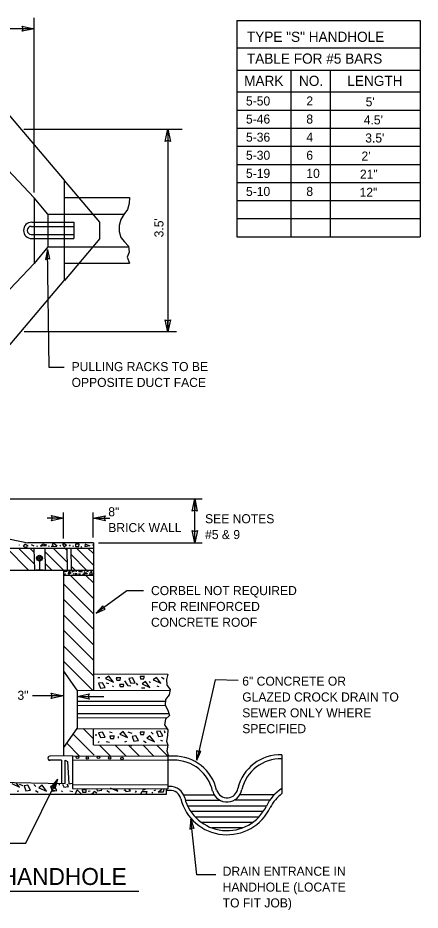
# Model space of a CAD drawing. Extents: x 19188 to 19495, y 20866 to 21061.
# Drawn here: x 19235.6 to 19272.9, y 20977 to 21059.6 of the extents above; entities that cross this region are included whole.
import ezdxf

# ---------------------------------------------------------------- set-up
doc = ezdxf.new("R2010")
doc.units = 0
doc.layers.add('G-ANNO-NOTE', color=7, linetype='Continuous')

msp = doc.modelspace()

# ---------------------------------------------------------------- linework, layer by layer
at = {"layer": 'G-ANNO-NOTE'}
for p, q in [((19237.159, 21043.431), (19237.159, 21059.598)), ((19255.924, 21059.35), (19272.913, 21059.35)), ((19255.924, 21059.35), (19255.924, 21039.329)), ((19272.913, 21059.35), (19272.913, 21039.329)), ((19237.159, 21058.588), (19211.313, 21058.588)), ((19237.159, 21058.588), (19236.128, 21058.588)), ((19255.924, 21056.815), (19272.913, 21056.815)), ((19255.924, 21054.755), (19272.913, 21054.755)), ((19260.919, 21054.755), (19260.919, 21039.329)), ((19264.589, 21054.755), (19264.589, 21039.329)), ((19255.924, 21052.734), (19272.913, 21052.734)), ((19233.362, 21052.314), (19239.943, 21044.556)), ((19255.924, 21051.058), (19272.913, 21051.058)), ((19236.185, 21049.277), (19250.872, 21049.277)), ((19249.541, 21049.277), (19249.541, 21030.515)), ((19249.541, 21049.277), (19249.541, 21048.246)), ((19255.924, 21049.382), (19272.913, 21049.382)), ((19231.626, 21048.77), (19237.159, 21042.927)), ((19255.924, 21047.707), (19272.913, 21047.707)), ((19255.924, 21046.031), (19272.913, 21046.031)), ((19239.943, 21044.556), (19239.943, 21035.275)), ((19243.233, 21040.677), (19239.972, 21044.521)), ((19255.924, 21044.356), (19272.913, 21044.356)), ((19237.159, 21042.927), (19237.159, 21036.845)), ((19238.424, 21041.43), (19237.159, 21042.927)), ((19239.943, 21042.949), (19245.981, 21042.949)), ((19255.924, 21042.68), (19272.913, 21042.68)), ((19238.424, 21041.43), (19238.424, 21038.393)), ((19238.424, 21041.43), (19245.472, 21041.43)), ((19255.924, 21041.004), (19272.913, 21041.004)), ((19236.888, 21040.291), (19240.821, 21040.291)), ((19236.928, 21040.67), (19240.821, 21040.67)), ((19240.821, 21040.67), (19240.821, 21039.152)), ((19243.233, 21039.158), (19243.233, 21040.677)), ((19236.169, 21039.911), (19236.169, 21039.911)), ((19236.508, 21039.911), (19236.508, 21039.911)), ((19236.887, 21039.532), (19240.821, 21039.532)), ((19236.927, 21039.152), (19240.821, 21039.152)), ((19243.233, 21039.158), (19239.952, 21035.286)), ((19255.924, 21039.329), (19272.913, 21039.329)), ((19238.424, 21038.393), (19237.159, 21036.845)), ((19238.424, 21038.393), (19245.86, 21038.393)), ((19239.943, 21036.874), (19245.981, 21036.874)), ((19237.159, 21036.845), (19231.626, 21031.052)), ((19233.362, 21027.508), (19239.943, 21035.275)), ((19249.541, 21030.515), (19249.541, 21031.546)), ((19236.229, 21030.545), (19250.328, 21030.545)), ((19232.92, 21015.045), (19252.718, 21015.045)), ((19252.034, 21010.995), (19252.034, 21015.047)), ((19252.034, 21015.047), (19252.034, 21014.017)), ((19239.887, 21011.389), (19239.887, 21013.778)), ((19242.623, 21011.463), (19242.623, 21013.778)), ((19239.887, 21013.256), (19238.359, 21013.256)), ((19239.887, 21013.256), (19238.857, 21013.256)), ((19242.623, 21013.256), (19244.151, 21013.256)), ((19242.623, 21013.256), (19243.653, 21013.256)), ((19234.041, 21011.501), (19236.572, 21010.995)), ((19252.034, 21010.995), (19252.034, 21012.025)), ((19211.192, 21010.489), (19242.647, 21010.489)), ((19236.647, 21008.464), (19234.622, 21010.489)), ((19235.696, 21010.489), (19237.184, 21009)), ((19242.647, 21010.995), (19236.572, 21010.995)), ((19236.77, 21010.489), (19237.166, 21010.092)), ((19237.204, 21008.478), (19237.164, 21010.468)), ((19238.216, 21008.493), (19238.177, 21010.476)), ((19238.918, 21010.489), (19240.209, 21009.197)), ((19239.991, 21010.489), (19240.188, 21010.292)), ((19240.242, 21008.492), (19240.202, 21010.482)), ((19240.622, 21008.464), (19240.582, 21010.48)), ((19242.647, 21008.907), (19241.066, 21010.489)), ((19242.647, 21009.981), (19242.139, 21010.489)), ((19242.647, 21010.995), (19242.647, 20997.329)), ((19243.105, 21010.995), (19252.718, 21010.995)), ((19239.869, 21008.464), (19238.189, 21010.143)), ((19242.016, 21008.464), (19240.607, 21009.874)), ((19237.642, 21009.31), (19237.642, 21008.487)), ((19238.795, 21008.464), (19238.218, 21009.04)), ((19240.943, 21008.464), (19240.615, 21008.792)), ((19211.192, 21008.464), (19242.647, 21008.464)), ((19237.991, 21008.459), (19237.354, 21008.459)), ((19239.862, 21008.464), (19239.862, 20991.333)), ((19242.647, 21007.957), (19239.862, 21007.957)), ((19239.964, 21008.401), (19240.136, 21008.418)), ((19240.014, 21008.286), (19239.964, 21008.401)), ((19240.217, 21008.319), (19240.014, 21008.286)), ((19240.136, 21008.418), (19240.217, 21008.319)), ((19240.328, 21008.103), (19240.359, 21008.252)), ((19240.39, 21008.054), (19240.328, 21008.103)), ((19240.338, 21008.332), (19240.517, 21008.332)), ((19240.359, 21008.252), (19240.521, 21008.252)), ((19240.42, 21008.153), (19240.39, 21008.054)), ((19240.511, 21008.153), (19240.42, 21008.153)), ((19240.521, 21008.252), (19240.511, 21008.153)), ((19242.647, 21005.837), (19240.535, 21007.948)), ((19240.673, 21008.269), (19240.765, 21008.418)), ((19240.886, 21008.385), (19240.673, 21008.269)), ((19240.765, 21008.418), (19240.886, 21008.385)), ((19241.129, 21008.12), (19240.927, 21008.12)), ((19240.927, 21008.12), (19240.947, 21008.037)), ((19240.947, 21008.037), (19241.069, 21008.02)), ((19241.069, 21008.02), (19241.129, 21008.12)), ((19241.271, 21008.099), (19241.45, 21008.099)), ((19241.282, 21008.286), (19241.363, 21008.401)), ((19241.616, 21008.286), (19241.282, 21008.286)), ((19241.363, 21008.401), (19241.616, 21008.286)), ((19241.678, 21008.054), (19241.779, 21008.12)), ((19241.768, 21008.054), (19241.678, 21008.054)), ((19241.819, 21008.054), (19241.768, 21008.054)), ((19241.779, 21008.12), (19241.789, 21008.186)), ((19241.789, 21008.186), (19241.88, 21008.236)), ((19241.9, 21008.136), (19241.819, 21008.054)), ((19241.88, 21008.236), (19241.971, 21008.203)), ((19241.992, 21008.136), (19241.9, 21008.136)), ((19242.647, 21007.269), (19241.957, 21007.959)), ((19241.971, 21008.203), (19241.992, 21008.136)), ((19242.073, 21008.369), (19242.154, 21008.385)), ((19242.103, 21008.269), (19242.073, 21008.369)), ((19242.154, 21008.385), (19242.103, 21008.269)), ((19242.458, 21008.252), (19242.296, 21008.103)), ((19242.296, 21008.103), (19242.407, 21008.02)), ((19242.366, 21008.332), (19242.545, 21008.332)), ((19242.407, 21008.02), (19242.56, 21008.136)), ((19242.56, 21008.136), (19242.458, 21008.252)), ((19242.647, 21004.405), (19239.865, 21007.187)), ((19242.647, 21002.973), (19239.868, 21005.753)), ((19242.647, 21001.541), (19239.87, 21004.318)), ((19242.647, 21000.109), (19239.872, 21002.884)), ((19242.647, 20998.677), (19239.875, 21001.449)), ((19242.564, 20997.329), (19239.878, 21000.015)), ((19239.879, 20999.103), (19241.12, 20997.329)), ((19242.647, 20998.845), (19249.549, 20998.833)), ((19243.245, 20998.468), (19243.066, 20998.468)), ((19244.078, 20998.633), (19243.78, 20998.413)), ((19243.78, 20998.413), (19244.495, 20998.081)), ((19244.495, 20998.081), (19244.078, 20998.633)), ((19245.863, 20997.749), (19245.566, 20998.191)), ((19246.28, 20998.468), (19245.923, 20998.413)), ((19245.923, 20998.413), (19246.102, 20997.971)), ((19246.518, 20998.026), (19246.28, 20998.468)), ((19247.471, 20998.136), (19247.173, 20997.915)), ((19247.887, 20997.584), (19247.471, 20998.136)), ((19247.947, 20998.026), (19247.828, 20998.136)), ((19248.482, 20998.523), (19248.185, 20998.302)), ((19248.185, 20998.302), (19248.899, 20997.971)), ((19248.899, 20997.971), (19248.482, 20998.523)), ((19249.197, 20998.357), (19248.959, 20998.523)), ((19241.132, 20997.329), (19241.094, 20997.366)), ((19241.12, 20997.329), (19249.73, 20997.314)), ((19241.128, 20997.329), (19241.128, 20993.785)), ((19243.483, 20998.026), (19243.126, 20997.971)), ((19243.126, 20997.971), (19243.304, 20997.529)), ((19243.304, 20997.529), (19243.721, 20997.584)), ((19243.721, 20997.584), (19243.483, 20998.026)), ((19244.078, 20997.915), (19243.84, 20997.971)), ((19244.435, 20997.639), (19244.495, 20997.749)), ((19246.102, 20997.695), (19245.863, 20997.749)), ((19246.102, 20997.971), (19246.518, 20998.026)), ((19246.756, 20997.805), (19246.637, 20997.971)), ((19247.411, 20997.529), (19247.114, 20997.529)), ((19247.173, 20997.915), (19247.887, 20997.584)), ((19248.721, 20997.639), (19248.542, 20997.695)), ((19239.862, 20996.815), (19236.997, 20996.815)), ((19239.862, 20996.815), (19238.832, 20996.815)), ((19241.128, 20996.765), (19243.613, 20996.765)), ((19241.128, 20996.765), (19242.159, 20996.765)), ((19241.119, 20996.316), (19249.281, 20996.303)), ((19241.146, 20995.936), (19249.28, 20995.923)), ((19241.146, 20995.177), (19249.622, 20995.163)), ((19241.146, 20994.797), (19249.462, 20994.784)), ((19241.115, 20993.785), (19239.867, 20992.015)), ((19242.713, 20991.326), (19240.764, 20993.274)), ((19241.115, 20993.785), (19249.46, 20993.771)), ((19242.647, 20992.824), (19241.686, 20993.785)), ((19242.647, 20992.264), (19242.647, 20993.785)), ((19242.888, 20993.109), (19242.888, 20993.275)), ((19243.483, 20993.441), (19243.126, 20993.385)), ((19243.126, 20993.385), (19243.304, 20992.943)), ((19243.721, 20992.999), (19243.483, 20993.441)), ((19244.376, 20993.385), (19244.138, 20993.441)), ((19245.387, 20993.496), (19245.09, 20993.275)), ((19245.09, 20993.275), (19245.804, 20992.943)), ((19245.804, 20992.943), (19245.387, 20993.496)), ((19246.221, 20993.33), (19245.863, 20993.441)), ((19246.578, 20993.109), (19246.221, 20993.054)), ((19246.816, 20992.667), (19246.578, 20993.109)), ((19247.887, 20993.109), (19247.59, 20992.888)), ((19248.304, 20992.557), (19247.887, 20993.109)), ((19248.006, 20993.441), (19248.185, 20993.275)), ((19248.839, 20993.551), (19248.482, 20993.496)), ((19248.482, 20993.496), (19248.661, 20993.054)), ((19248.661, 20993.054), (19249.077, 20993.109)), ((19249.077, 20993.109), (19248.839, 20993.551)), ((19249.197, 20993.606), (19249.256, 20993.385)), ((19241.34, 20991.267), (19240.168, 20992.438)), ((19242.647, 20992.264), (19249.538, 20992.252)), ((19243.126, 20992.502), (19243.185, 20992.612)), ((19244.206, 20991.265), (19243.215, 20992.256)), ((19243.304, 20992.943), (19243.721, 20992.999)), ((19244.138, 20992.502), (19243.84, 20992.557)), ((19244.971, 20992.888), (19244.971, 20993.054)), ((19245.566, 20992.557), (19245.745, 20992.612)), ((19246.221, 20993.054), (19246.399, 20992.612)), ((19246.399, 20992.612), (19246.816, 20992.667)), ((19247.53, 20992.446), (19247.292, 20992.612)), ((19247.59, 20992.888), (19248.304, 20992.557)), ((19249.078, 20992.612), (19248.899, 20992.667)), ((19245.645, 20991.258), (19244.667, 20992.236)), ((19246.885, 20991.258), (19245.907, 20992.236)), ((19246.191, 20992.144), (19246.119, 20992.215)), ((19248.225, 20991.258), (19247.247, 20992.236)), ((19249.498, 20991.258), (19248.521, 20992.236)), ((19239.69, 20990.86), (19238.596, 20990.844)), ((19240.713, 20991.255), (19238.617, 20991.224)), ((19239.69, 20990.86), (19239.69, 20988.706)), ((19240.021, 20988.692), (19240.031, 20990.843)), ((19240.031, 20990.843), (19240.233, 20990.734)), ((19240.233, 20990.734), (19240.367, 20988.664)), ((19240.713, 20991.255), (19240.707, 20988.217)), ((19240.712, 20990.875), (19249.536, 20990.86)), ((19240.713, 20991.255), (19249.536, 20991.24)), ((19250.107, 20990.855), (19249.521, 20990.856)), ((19249.536, 20991.24), (19249.549, 20988.202)), ((19250.107, 20991.234), (19249.561, 20991.229)), ((19260.113, 20991.356), (19260.113, 20987.759)), ((19211.192, 20989.226), (19240.021, 20988.692)), ((19235.09, 20988.69), (19235.805, 20988.358)), ((19235.805, 20988.358), (19235.502, 20988.759)), ((19236.152, 20988.483), (19235.795, 20988.593)), ((19236.579, 20988.524), (19236.222, 20988.469)), ((19236.222, 20988.469), (19236.4, 20988.027)), ((19236.817, 20988.082), (19236.579, 20988.524)), ((19237.133, 20988.593), (19237.311, 20988.428)), ((19237.888, 20988.524), (19237.591, 20988.303)), ((19237.591, 20988.303), (19238.304, 20987.971)), ((19238.304, 20987.971), (19237.888, 20988.524)), ((19239.024, 20988.479), (19238.667, 20988.424)), ((19238.667, 20988.424), (19238.846, 20987.982)), ((19239.262, 20988.038), (19239.024, 20988.479)), ((19239.495, 20988.524), (19239.495, 20988.69)), ((19239.797, 20988.642), (19239.906, 20988.371)), ((19239.912, 20988.358), (19240.328, 20988.413)), ((19240.328, 20988.413), (19240.213, 20988.628)), ((19240.367, 20988.664), (19240.669, 20988.718)), ((19240.707, 20988.217), (19249.549, 20988.202)), ((19240.708, 20988.597), (19249.532, 20988.582)), ((19240.97, 20987.683), (19241.138, 20988.119)), ((19241.138, 20988.119), (19241.506, 20987.737)), ((19242.966, 20988.127), (19243.007, 20988.027)), ((19243.424, 20988.082), (19243.384, 20988.156)), ((19244.197, 20988.303), (19244.911, 20987.971)), ((19244.911, 20987.971), (19244.744, 20988.193)), ((19245.582, 20988.127), (19245.656, 20987.944)), ((19246.072, 20988), (19245.96, 20988.208)), ((19247.203, 20988.064), (19247.471, 20988.173)), ((19248.644, 20987.901), (19248.979, 20988.173)), ((19249.171, 20988.185), (19249.113, 20987.901)), ((19249.414, 20987.708), (19249.414, 20988.202)), ((19249.697, 20988.426), (19249.558, 20988.426)), ((19207.649, 20987.708), (19249.414, 20987.708)), ((19235.567, 20987.971), (19235.745, 20988.027)), ((19236.4, 20988.027), (19236.817, 20988.082)), ((19237.531, 20987.861), (19237.293, 20988.027)), ((19238.846, 20987.982), (19239.262, 20988.038)), ((19239.078, 20988.027), (19238.9, 20988.082)), ((19239.733, 20987.916), (19239.793, 20988.027)), ((19240.745, 20987.916), (19240.447, 20987.971)), ((19242.173, 20987.971), (19242.352, 20988.027)), ((19242.545, 20987.737), (19242.344, 20987.683)), ((19242.713, 20987.955), (19242.545, 20987.737)), ((19242.947, 20987.792), (19242.713, 20987.955)), ((19243.007, 20988.027), (19243.424, 20988.082)), ((19244.138, 20987.861), (19243.9, 20988.027)), ((19245.685, 20988.027), (19245.507, 20988.082)), ((19245.656, 20987.944), (19246.072, 20988)), ((19246.533, 20987.846), (19246.633, 20988.01)), ((19247.035, 20987.683), (19247.136, 20987.955)), ((19247.136, 20987.955), (19247.605, 20987.955)), ((19247.605, 20987.955), (19247.538, 20987.737)), ((19248.141, 20987.792), (19248.074, 20987.901)), ((19248.409, 20988.064), (19248.242, 20988.01)), ((19249.113, 20987.901), (19248.644, 20987.901)), ((19249.738, 20988.056), (19249.422, 20988.056)), ((19251.008, 20987.645), (19253.824, 20987.645)), ((19259.375, 20987.645), (19256.237, 20987.645)), ((19251.21, 20987.139), (19254.367, 20987.139)), ((19251.371, 20986.633), (19258.651, 20986.633)), ((19258.912, 20987.139), (19255.674, 20987.139)), ((19251.652, 20986.126), (19258.389, 20986.126)), ((19252.074, 20985.62), (19257.967, 20985.62)), ((19252.637, 20985.114), (19257.384, 20985.114)), ((19253.603, 20984.608), (19256.438, 20984.608)), ((19213.987, 20978.708), (19246.848, 20978.708))]:
    msp.add_line(p, q, dxfattribs=at)
for points in [[(19236.128, 21058.587), (19236.037, 21058.834), (19237.159, 21058.588), (19236.04, 21058.352), (19236.128, 21058.587)], [(19249.541, 21048.246), (19249.295, 21048.156), (19249.541, 21049.277), (19249.777, 21048.158), (19249.541, 21048.246)], [(19245.981, 21042.949), (19245.957, 21042.407), (19245.811, 21041.854), (19245.472, 21041.381), (19245.181, 21040.909), (19245.036, 21040.356), (19245.036, 21039.804), (19245.181, 21039.252), (19245.521, 21038.858), (19245.908, 21038.464), (19245.957, 21037.912), (19245.763, 21037.438), (19245.981, 21036.874), (19245.981, 21036.874)], [(19239.921, 21027.207), (19238.536, 21027.207), (19238.382, 21038.135)], [(19249.541, 21031.546), (19249.788, 21031.636), (19249.541, 21030.515), (19249.306, 21031.634), (19249.541, 21031.546)], [(19252.034, 21014.017), (19251.788, 21013.927), (19252.034, 21015.047), (19252.269, 21013.929), (19252.034, 21014.017)], [(19238.857, 21013.255), (19238.766, 21013.502), (19239.887, 21013.256), (19238.769, 21013.02), (19238.857, 21013.255)], [(19243.654, 21013.256), (19243.744, 21013.009), (19242.623, 21013.256), (19243.741, 21013.491), (19243.654, 21013.256)], [(19252.034, 21012.026), (19252.28, 21012.116), (19252.034, 21010.995), (19251.799, 21012.113), (19252.034, 21012.026)], [(19235.783, 21010.768), (19235.783, 21010.811)], [(19236.596, 21010.683), (19236.281, 21010.853), (19236.15, 21010.683), (19236.386, 21010.556), (19236.517, 21010.641)], [(19237.147, 21010.683), (19236.911, 21010.811)], [(19237.435, 21010.641), (19237.461, 21010.726)], [(19238.326, 21010.768), (19237.985, 21010.853), (19237.75, 21010.683), (19238.012, 21010.726), (19238.3, 21010.726)], [(19238.51, 21010.641), (19238.536, 21010.726)], [(19239.296, 21010.683), (19239.008, 21010.896), (19238.825, 21010.853), (19238.929, 21010.683), (19238.719, 21010.641), (19239.27, 21010.683)], [(19239.637, 21010.683), (19239.532, 21010.768)], [(19240.161, 21010.726), (19239.951, 21010.896), (19239.794, 21010.853), (19239.951, 21010.598), (19240.161, 21010.811)], [(19240.528, 21010.683), (19240.423, 21010.811)], [(19240.764, 21010.641), (19240.791, 21010.726)], [(19241.315, 21010.853), (19241, 21010.853), (19240.974, 21010.641), (19241.289, 21010.641), (19241.341, 21010.853)], [(19241.577, 21010.556), (19241.525, 21010.641)], [(19242.337, 21010.683), (19241.892, 21010.853), (19241.839, 21010.641), (19242.285, 21010.726)], [(19242.547, 21010.811), (19242.521, 21010.726)], [(19240.066, 21008.063), (19240.013, 21008.148)], [(19240.809, 21008.076), (19240.835, 21008.162)], [(19241.09, 21008.279), (19241.037, 21008.364)], [(19241.813, 21008.275), (19241.839, 21008.36)], [(19242.104, 21008.08), (19242.051, 21008.165)], [(19247.281, 21006.551), (19245.743, 21006.551), (19242.897, 21004.473)], [(19245.18, 20998.485), (19244.761, 20998.485), (19244.814, 20998.272), (19245.128, 20998.272), (19245.154, 20998.442)], [(19247.383, 20998.595), (19246.963, 20998.595), (19247.016, 20998.383), (19247.33, 20998.383), (19247.357, 20998.553)], [(19249.549, 20998.833), (19249.406, 20998.323), (19249.46, 20997.797), (19249.765, 20997.388), (19249.657, 20996.891), (19249.334, 20996.481), (19249.28, 20995.955), (19249.549, 20995.488), (19249.693, 20994.991), (19249.316, 20994.64), (19249.244, 20994.114), (19249.531, 20993.676), (19249.495, 20993.15), (19249.406, 20992.624), (19249.538, 20992.252)], [(19256.065, 20998.23), (19253.91, 20998.307), (19252.218, 20990.842)], [(19245.478, 20997.877), (19245.059, 20997.877), (19245.111, 20997.664), (19245.426, 20997.664), (19245.452, 20997.835)], [(19238.832, 20996.815), (19238.742, 20997.061), (19239.862, 20996.815), (19238.744, 20996.58), (19238.832, 20996.815)], [(19242.159, 20996.765), (19242.249, 20996.518), (19241.128, 20996.765), (19242.247, 20997), (19242.159, 20996.765)], [(19247.383, 20993.458), (19246.963, 20993.458), (19247.016, 20993.245), (19247.33, 20993.245), (19247.357, 20993.416)], [(19244.585, 20993.071), (19244.166, 20993.071), (19244.218, 20992.858), (19244.533, 20992.858), (19244.559, 20993.029)], [(19249.538, 20992.252), (19249.448, 20991.715), (19249.616, 20991.224), (19249.536, 20991.24)], [(19232.151, 20983.165), (19236.381, 20983.165), (19239.304, 20989.091)], [(19242.013, 20988.104), (19241.593, 20988.104), (19241.646, 20987.891), (19241.961, 20987.891), (19241.987, 20988.061)], [(19253.981, 20980.231), (19252.212, 20980.231), (19251.673, 20985.388)]]:
    msp.add_lwpolyline(points, dxfattribs=at)
for points in [[(19238.198, 21037.235), (19238.394, 21037.31), (19238.382, 21038.135), (19238.583, 21037.242), (19238.394, 21037.31), (19238.382, 21038.135)], [(19243.738, 21004.843), (19243.563, 21004.959), (19242.897, 21004.473), (19243.509, 21005.153), (19243.563, 21004.959), (19242.897, 21004.473)], [(19252.609, 20991.673), (19252.401, 20991.646), (19252.218, 20990.842), (19252.232, 20991.756), (19252.401, 20991.646), (19252.218, 20990.842)], [(19238.73, 20988.374), (19238.939, 20988.351), (19239.304, 20989.091), (19239.077, 20988.205), (19238.939, 20988.351), (19239.304, 20989.091)], [(19251.57, 20984.475), (19251.758, 20984.567), (19251.673, 20985.388), (19251.953, 20984.517), (19251.758, 20984.567), (19251.673, 20985.388)]]:
    msp.add_lwpolyline(points, close=True, dxfattribs=at)
for centre, radius in [((19237.65, 21009.572), 0.266), ((19237.642, 21009.579), 0.19), ((19237.642, 21009.579), 0.0759), ((19241.171, 20991.115), 0.114), ((19242.076, 20991.061), 0.114), ((19243.115, 20991.115), 0.114), ((19244.154, 20991.061), 0.114), ((19245.293, 20991.006), 0.114)]:
    msp.add_circle(centre, radius, dxfattribs=at)
for centre, radius, start, end in [((19236.928, 21039.911), 0.759, 90, 180), ((19236.888, 21039.911), 0.38, 90, 180), ((19236.928, 21039.911), 0.759, 180, 269.99999), ((19236.887, 21039.911), 0.379, 180, 270), ((19238.607, 20991.035), 0.19, 86.99693, 275.21188), ((19250.107, 20987.185), 3.67, 12.36577, 90.3719), ((19250.107, 20987.185), 4.05, 12.60623, 90.33586), ((19259.97, 20987.309), 4.05, 87.98106, 167.00836), ((19259.97, 20987.309), 3.67, 87.98079, 166.8227), ((19249.754, 20987.035), 1.392, 14.12833, 92.34491), ((19255.024, 20988.378), 1.392, 197.01005, 350.40939), ((19255.024, 20988.378), 1.012, 197.79093, 351.01229), ((19262.308, 20984.831), 4.05, 123.06222, 153.9668), ((19249.75, 20987.042), 1.012, 13.33654, 92.19817), ((19255.024, 20988.378), 4.05, 194.3466, 334.10825), ((19262.292, 20984.805), 3.67, 126.42255, 152.74551), ((19255.024, 20988.378), 4.43, 194.41932, 334.71911)]:
    msp.add_arc(centre, radius, start, end, dxfattribs=at)

# ---------------------------------------------------------------- texts
for s, height, p in [('TYPE "S" HANDHOLE', 0.94259, (19256.863, 21057.374)), ('TABLE FOR #5 BARS', 0.94259, (19256.863, 21055.353)), ('MARK', 0.9426, (19256.607, 21053.293)), ('NO.', 0.9426, (19261.687, 21053.293)), ('LENGTH', 0.9426, (19266.169, 21053.293)), ('5-50', 0.8379, (19256.778, 21051.483)), ('2', 0.838, (19262.37, 21051.483)), ("5'", 0.8379, (19267.864, 21051.406)), ('5-46', 0.8379, (19256.778, 21049.807)), ('8', 0.838, (19262.37, 21049.807)), ("4.5'", 0.8379, (19267.689, 21049.73)), ('5-36', 0.8379, (19256.778, 21048.131)), ('4', 0.838, (19262.37, 21048.131)), ("3.5'", 0.8379, (19267.829, 21048.054)), ('5-30', 0.8379, (19256.778, 21046.456)), ('6', 0.838, (19262.37, 21046.456)), ("2'", 0.8379, (19267.478, 21046.378)), ('5-19', 0.8379, (19256.778, 21044.78)), ('10', 0.8379, (19262.37, 21044.78)), ('21"', 0.8379, (19267.337, 21044.703)), ('5-10', 0.8379, (19256.778, 21043.105)), ('8', 0.838, (19262.37, 21043.105)), ('12"', 0.8379, (19267.302, 21043.027)), ('PULLING RACKS TO BE ', 0.83785, (19240.624, 21026.883)), ('OPPOSITE DUCT FACE', 0.83785, (19240.624, 21025.418)), ('8"', 0.8379, (19244.023, 21013.44)), ('SEE NOTES', 0.8379, (19252.991, 21012.795)), ('BRICK WALL', 0.8379, (19244.023, 21011.973)), ('#5 & 9', 0.8379, (19252.991, 21011.329)), ('CORBEL NOT REQUIRED', 0.83785, (19247.98, 21006.14)), ('FOR REINFORCED', 0.83785, (19247.98, 21004.674)), ('CONCRETE ROOF', 0.83785, (19247.98, 21003.207)), ('6" CONCRETE OR ', 0.83785, (19256.434, 20997.754)), ('3"', 0.8379, (19235.607, 20996.443)), ('GLAZED CROCK DRAIN TO ', 0.83785, (19256.434, 20996.287)), ('SEWER ONLY WHERE ', 0.83785, (19256.434, 20994.82)), ('SPECIFIED', 0.8379, (19256.434, 20993.354)), ('SECTION TYPE "S" HANDHOLE', 1.57098, (19214.585, 20979.297)), ('DRAIN ENTRANCE IN', 0.83785, (19254.622, 20980.149)), ('HANDHOLE (LOCATE', 0.83785, (19254.622, 20978.683)), ('TO FIT JOB)', 0.83785, (19254.622, 20977.217))]:
    msp.add_text(s, height=height, dxfattribs=at).set_placement(p)
msp.add_text("3.5'", height=0.8379, rotation=90, dxfattribs=at).set_placement((19249.135, 21039.27))

doc.saveas('drawing.dxf')
